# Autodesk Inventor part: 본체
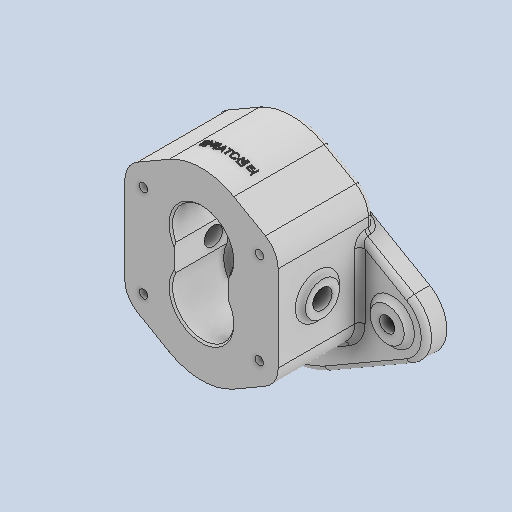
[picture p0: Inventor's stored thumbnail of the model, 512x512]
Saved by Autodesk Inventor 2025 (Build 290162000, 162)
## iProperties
Created: 2026-08
Part Number: 본체
Material: 일반
Document SubType Name: Modeling
Designer: KDI
Density: 1 g/cm^3
Appearance: 기본값
Author: jhkim
Sending System: Autodesk Inventor 2027
Preprocessor: ST-DEVELOPER v20.1
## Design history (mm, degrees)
feature "솔리드1"
node "솔리드2"
